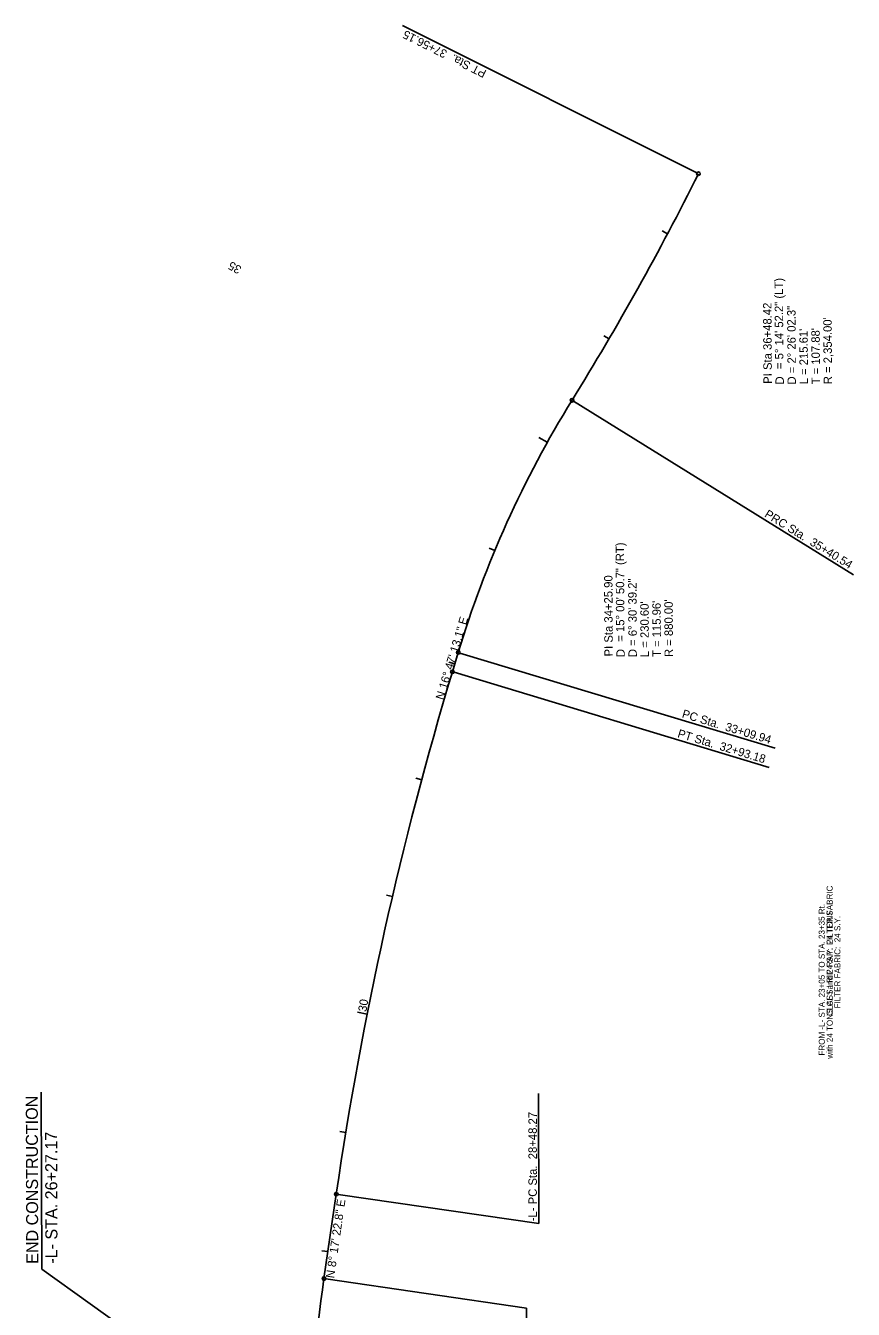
# Model space of a CAD drawing. Extents: x 1373164 to 1374172, y 550391 to 553180.
# Drawn here: x 1373473 to 1374161, y 552113 to 553180 of the extents above; entities that cross this region are included whole.
import ezdxf

# ---------------------------------------------------------------- set-up
doc = ezdxf.new("R2010")
doc.units = 0
for name, color, linetype in [('Exist Building Cogo Point CELL', 7, 'Continuous'), ('Exist Roads EOP Other Cogo Comment', 7, 'Continuous'), ('Exist Roads EOP Other Cogo Elevation', 7, 'Continuous'), ('Exist Structure Major Deck Tunnel Box Culvert Cogo Number', 7, 'Continuous'), ('Exist Structure Minor Pipes RCP 18 Inch Cogo Comment', 7, 'Continuous'), ('Exist Structure Minor Pipes RCP 18 Inch Cogo Elevation', 7, 'Continuous'), ('Exist Structure Minor Pipes RCP 18 Inch Cogo Number', 7, 'Continuous'), ('Exist Structure Minor Pipes RCP 18 Inch Cogo Point CELL', 7, 'Continuous'), ('Exist Utilities Sanitary Sewer Manhole Cogo Elevation', 7, 'Continuous')]:
    doc.layers.add(name, color=color, linetype=linetype)

msp = doc.modelspace()

# ---------------------------------------------------------------- linework, layer by layer
at = {"layer": 'Exist Building Cogo Point CELL'}
for p, q in [((1374006.6, 553006.8), (1374002.1, 553009.2)), ((1373957.9, 552919.5), (1373953.6, 552922)), ((1373862.9, 552743.7), (1373858.3, 552745.6)), ((1373829.7, 552649.5), (1373824.9, 552650.9)), ((1373802.2, 552553.3), (1373797.4, 552554.6)), ((1373777.9, 552456.3), (1373773.1, 552457.4)), ((1373739.1, 552260.1), (1373734.2, 552261)), ((1373724.3, 552161.3), (1373719.3, 552162))]:
    msp.add_line(p, q, dxfattribs=at)
at = {"layer": 'Exist Roads EOP Other Cogo Elevation'}
for p, q in [((1373827.7, 552642.9), (1373832.6, 552659)), ((1373721, 552138.9), (1373731.2, 552209))]:
    msp.add_line(p, q, dxfattribs=at)
for centre, radius, start, end in [((1371926.5, 554109), 2354, 328.199, 333.4468), ((1374675.1, 552404.8), 880, 148.199, 163.213), ((1376699.9, 551776.5), 3000, 163.213, 171.7103), ((1375240, 551917.6), 1535, 171.7103, 182.9585)]:
    msp.add_arc(centre, radius, start, end, dxfattribs=at)
at = {"layer": 'Exist Structure Minor Pipes RCP 18 Inch Cogo Comment'}
for p, q in [((1373906.6, 552833.6), (1373899.6, 552837.5)), ((1373756.9, 552358.6), (1373749, 552360.1))]:
    msp.add_line(p, q, dxfattribs=at)
at = {"layer": 'Exist Structure Minor Pipes RCP 18 Inch Cogo Number'}
for p, q in [((1374030.9, 553057.4), (1373786.3, 553179.7)), ((1373928.4, 552867.8), (1374160.9, 552723.6)), ((1373834, 552658.5), (1374095.9, 552579.5)), ((1373829.2, 552642.5), (1374091, 552563.5)), ((1373899.5, 552184.5), (1373899.4, 552292.7)), ((1373732.7, 552208.8), (1373899.5, 552184.5)), ((1373722.5, 552138.7), (1373889.2, 552114.4)), ((1373889.3, 552011), (1373889.2, 552114.4))]:
    msp.add_line(p, q, dxfattribs=at)
for centre in [(1374032.2, 553056.7), (1373927.2, 552868.5), (1373832.6, 552659), (1373827.7, 552642.9), (1373731.2, 552209), (1373721, 552138.9)]:
    msp.add_circle(centre, 1.5, dxfattribs=at)
at = {"layer": 'Exist Utilities Sanitary Sewer Manhole Cogo Elevation'}
for p, q in [((1373486.5, 552146.6), (1373486.1, 552293.8)), ((1373706.7, 551989.4), (1373486.5, 552146.6))]:
    msp.add_line(p, q, dxfattribs=at)

# ---------------------------------------------------------------- texts
at = {"layer": 'Exist Roads EOP Other Cogo Comment'}
for s, rotation, p in [('N 16%%d 47\' 13.1" E', 73.213, (1373820.3, 552619.1)), ('N 8%%d 17\' 22.8" E', 81.7103, (1373729.4, 552138.8))]:
    msp.add_text(s, height=7, rotation=rotation, dxfattribs=at).set_placement(p)
at = {"layer": 'Exist Structure Major Deck Tunnel Box Culvert Cogo Number'}
for s, p in [('with 24 TONS CL I and 24 S.Y. FILTER FABRIC', (1374143.8, 552321.5)), (' FROM -L- STA. 23+05 TO STA. 23+35 Rt.', (1374137.2, 552322.3)), ('CLASS I RIP RAP:  24 TONS', (1374143.7, 552357)), ('FILTER FABRIC:  24 S.Y.', (1374150.2, 552363.3))]:
    msp.add_text(s, height=5, rotation=90.0509, dxfattribs=at).set_placement(p)
at = {"layer": 'Exist Structure Minor Pipes RCP 18 Inch Cogo Elevation'}
for s, rotation, p in [('35', 150.8384, (1373653.1, 552979.1)), ('30', 80.4975, (1373756.2, 552360.1))]:
    msp.add_text(s, height=7, rotation=rotation, dxfattribs=at).set_placement(p)
at = {"layer": 'Exist Structure Minor Pipes RCP 18 Inch Cogo Number'}
for s, height, rotation, p in [('PT Sta.  37+56.15', 7, 153.4468, (1373856.6, 553142.3)), ('PRC Sta.  35+40.54', 7, 328.199, (1374086.5, 552772.1)), ('PC Sta.  33+09.94', 7, 343.213, (1374018, 552605.1)), ('PT Sta.  32+93.18', 7, 343.213, (1374014.3, 552588.7)), ('END CONSTRUCTION', 10, 90.1567, (1373483.6, 552151.1)), ('-L- PC Sta.  28+48.27', 7, 89.9959, (1373897.9, 552186.5)), ('-L- STA. 26+27.17', 10, 90.1567, (1373499.6, 552151.2))]:
    msp.add_text(s, height=height, rotation=rotation, dxfattribs=at).set_placement(p)
at = {"layer": 'Exist Structure Minor Pipes RCP 18 Inch Cogo Point CELL'}
for s, rotation, p in [('= 5%%d 14\' 52.2" (LT)', 90.3034, (1374102.8, 552894.4)), ('PI Sta 36+48.42', 90.3034, (1374093.2, 552882.2)), ('D = 2%%d 26\' 02.3"', 90.3034, (1374113.2, 552881.6)), ("R = 2,354.00'", 90.3034, (1374143.2, 552881.8)), ("L = 215.61'", 90.3034, (1374123.2, 552881.7)), ("T = 107.88'", 90.3034, (1374133.2, 552881.7)), ('D', 90.3034, (1374103.2, 552881.6)), ('= 15%%d 00\' 50.7" (RT)', 90.2081, (1373970.7, 552667.9)), ('PI Sta 34+25.90', 90.2081, (1373961, 552655.7)), ('D = 6%%d 30\' 39.2"', 90.2081, (1373981, 552655.1)), ("L = 230.60'", 90.2081, (1373991, 552655.1)), ("T = 115.96'", 90.2081, (1374001, 552655.2)), ("R = 880.00'", 90.2081, (1374011, 552655.2)), ('D', 90.2081, (1373971, 552655.1))]:
    msp.add_text(s, height=7, rotation=rotation, dxfattribs=at).set_placement(p)

doc.saveas('drawing.dxf')
